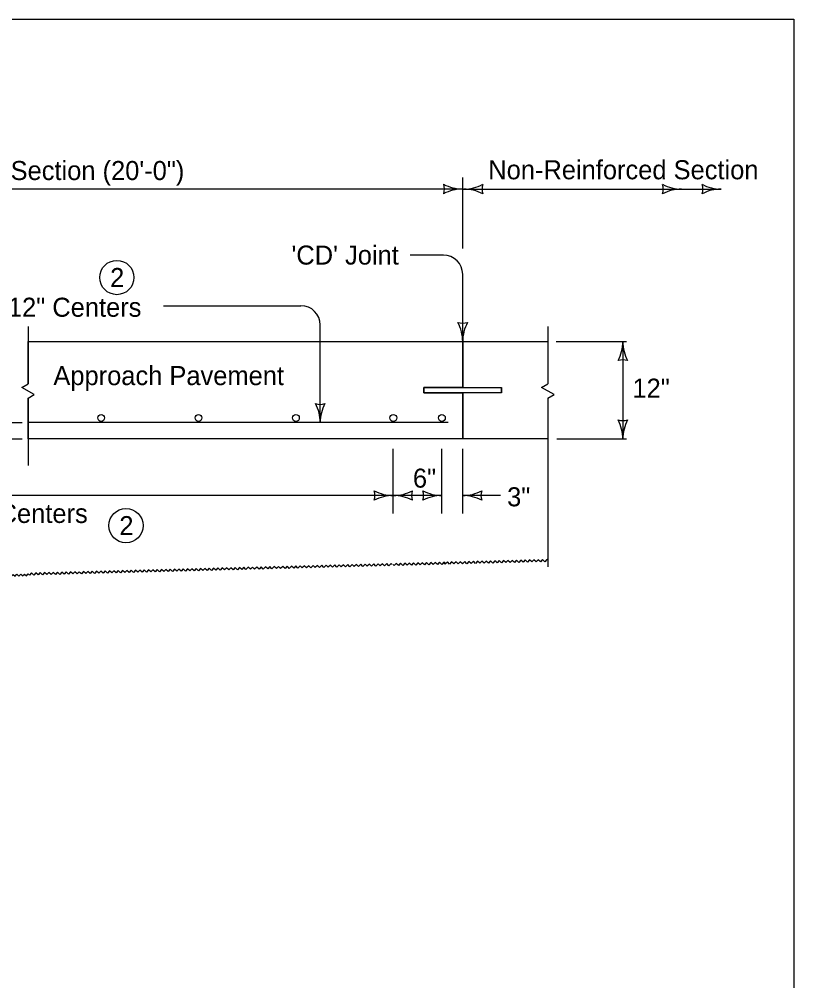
# Model space of a CAD drawing. Extents: x 10130 to 81668, y 5440 to 21644.
# Drawn here: x 12454 to 13268, y 8934 to 9944 of the extents above; entities that cross this region are included whole.
import ezdxf

# ---------------------------------------------------------------- set-up
doc = ezdxf.new("R2010")
doc.units = 0
for name, color, linetype in [('dsnStdBlockModified', 7, 'Continuous'), ('dsnStdBlockNotModified', 7, 'Continuous'), ('dsnStdBorder', 7, 'Continuous'), ('Level 3', 7, 'Continuous'), ('SheetBorder', 7, 'Continuous')]:
    doc.layers.add(name, color=color, linetype=linetype)

msp = doc.modelspace()

# ---------------------------------------------------------------- linework, layer by layer
at = {"layer": 'dsnStdBlockModified'}
for p, q in [((12919.6, 9703.1), (12919.6, 9777.8)), ((11951, 9765.7), (12919.6, 9765.7)), ((12919.6, 9765.6), (13191.2, 9765.6)), ((12899.4, 9696.3), (12864.5, 9696.3)), ((12919.6, 9605.5), (12919.6, 9676.1)), ((12605.1, 9643.1), (12749.7, 9643.1)), ((12769.9, 9520.3), (12769.9, 9622.9)), ((12462.9, 9561.1), (12462.9, 9605.5)), ((12462.9, 9605.5), (12919.6, 9605.5)), ((12462.9, 9605.5), (12919.6, 9605.5)), ((12919.6, 9605.5), (12919.6, 9557.2)), ((12919.6, 9605.5), (13009.1, 9605.5)), ((13017.9, 9605.4), (13091.7, 9605.4)), ((13087.9, 9605.4), (13087.9, 9503.1)), ((12462.9, 9561.1), (12462.9, 9561.1)), ((12919.6, 9557.2), (12878.7, 9557.2)), ((12878.7, 9557.2), (12878.7, 9551.5)), ((12878.7, 9557.2), (12878.7, 9551.5)), ((12960.5, 9551.5), (12960.5, 9557.2)), ((12462.9, 9503.2), (12462.9, 9545.9)), ((12878.7, 9551.5), (12919.6, 9551.5)), ((12919.6, 9551.5), (12919.6, 9503.2)), ((12433.7, 9520.3), (12456.6, 9520.3)), ((12433.7, 9503.2), (12456.6, 9503.2)), ((12919.6, 9503.2), (12462.9, 9503.2)), ((12919.6, 9503.2), (12462.9, 9503.2)), ((13009.1, 9503.2), (12919.6, 9503.2)), ((13018.4, 9503.1), (13091.7, 9503.1)), ((12846.7, 9424.7), (12846.7, 9492.7)), ((12897.8, 9424.7), (12897.8, 9492.7)), ((12919.6, 9424.7), (12919.6, 9492.7)), ((12846.7, 9443.7), (12023.9, 9443.7)), ((12897.8, 9443.7), (12846.7, 9443.7)), ((12886.4, 9443.7), (12846.7, 9443.7)), ((12959.4, 9443.7), (12919.6, 9443.7))]:
    msp.add_line(p, q, dxfattribs=at)
for points in [[(12462.9, 9545.9), (12469.4, 9549.7), (12456.3, 9557.3), (12462.9, 9561.1)], [(12901.1, 9372.6), (12899.9, 9373.7), (12897.7, 9371.4), (12895.3, 9373.6), (12893.1, 9371.3), (12890.8, 9373.5), (12888.6, 9371.2), (12886.2, 9373.4), (12884, 9371), (12881.7, 9373.3), (12879.5, 9370.9), (12877.1, 9373.1), (12874.9, 9370.8), (12872.6, 9373), (12870.4, 9370.7), (12868, 9372.9), (12865.8, 9370.6), (12863.5, 9372.8), (12861.3, 9370.5), (12858.9, 9372.7), (12856.7, 9370.3), (12854.4, 9372.5), (12852.2, 9370.2), (12849.8, 9372.4), (12847.6, 9370.1), (12846.4, 9371.2)], [(12954.7, 9374), (12953.5, 9375.2), (12951.3, 9372.8), (12949, 9375), (12946.8, 9372.7), (12944.4, 9374.9), (12942.2, 9372.6), (12939.9, 9374.8), (12937.7, 9372.5), (12935.3, 9374.7), (12933.1, 9372.4), (12930.8, 9374.6), (12928.6, 9372.2), (12926.2, 9374.4), (12924, 9372.1), (12921.7, 9374.3), (12919.5, 9372), (12917.1, 9374.2), (12914.9, 9371.9), (12912.6, 9374.1), (12910.4, 9371.8), (12908, 9374), (12905.8, 9371.6), (12903.5, 9373.9), (12901.3, 9371.5), (12900.1, 9372.6)], [(13009.3, 9375.5), (13008.1, 9376.6), (13005.9, 9374.2), (13003.6, 9376.5), (13001.4, 9374.1), (12999, 9376.3), (12996.8, 9374), (12994.5, 9376.2), (12992.3, 9373.9), (12989.9, 9376.1), (12987.7, 9373.8), (12985.4, 9376), (12983.2, 9373.7), (12980.8, 9375.9), (12978.6, 9373.5), (12976.3, 9375.8), (12974.1, 9373.4), (12971.7, 9375.6), (12969.5, 9373.3), (12967.2, 9375.5), (12965, 9373.2), (12962.6, 9375.4), (12960.4, 9373.1), (12958.1, 9375.3), (12955.9, 9372.9), (12954.7, 9374)], [(12517.8, 9362.6), (12516.7, 9363.7), (12514.5, 9361.4), (12512.1, 9363.6), (12509.9, 9361.3), (12507.6, 9363.5), (12505.4, 9361.2), (12503, 9363.4), (12500.8, 9361.1), (12498.5, 9363.3), (12496.3, 9360.9), (12493.9, 9363.2), (12491.7, 9360.8), (12489.4, 9363), (12487.2, 9360.7), (12484.8, 9362.9), (12482.6, 9360.6), (12480.3, 9362.8), (12478.1, 9360.5), (12475.7, 9362.7), (12473.5, 9360.3), (12471.2, 9362.6), (12469, 9360.2), (12466.6, 9362.4), (12464.4, 9360.1), (12463.2, 9361.2)], [(12572.4, 9364.1), (12571.3, 9365.2), (12569.1, 9362.8), (12566.7, 9365.1), (12564.5, 9362.7), (12562.2, 9364.9), (12560, 9362.6), (12557.6, 9364.8), (12555.4, 9362.5), (12553.1, 9364.7), (12550.9, 9362.4), (12548.5, 9364.6), (12546.3, 9362.2), (12544, 9364.5), (12541.8, 9362.1), (12539.4, 9364.3), (12537.2, 9362), (12534.9, 9364.2), (12532.7, 9361.9), (12530.3, 9364.1), (12528.1, 9361.8), (12525.8, 9364), (12523.6, 9361.7), (12521.2, 9363.9), (12519, 9361.5), (12517.8, 9362.6)], [(12627.1, 9365.5), (12625.9, 9366.6), (12623.7, 9364.3), (12621.3, 9366.5), (12619.1, 9364.2), (12616.8, 9366.4), (12614.6, 9364), (12612.2, 9366.2), (12610, 9363.9), (12607.7, 9366.1), (12605.5, 9363.8), (12603.1, 9366), (12600.9, 9363.7), (12598.6, 9365.9), (12596.4, 9363.6), (12594, 9365.8), (12591.8, 9363.4), (12589.5, 9365.6), (12587.3, 9363.3), (12584.9, 9365.5), (12582.7, 9363.2), (12580.4, 9365.4), (12578.2, 9363.1), (12575.8, 9365.3), (12573.6, 9363), (12572.4, 9364.1)], [(12681.7, 9366.9), (12680.5, 9368), (12678.3, 9365.7), (12675.9, 9367.9), (12673.7, 9365.6), (12671.4, 9367.8), (12669.2, 9365.5), (12666.8, 9367.7), (12664.6, 9365.3), (12662.3, 9367.6), (12660.1, 9365.2), (12657.7, 9367.4), (12655.5, 9365.1), (12653.2, 9367.3), (12651, 9365), (12648.6, 9367.2), (12646.4, 9364.9), (12644.1, 9367.1), (12641.9, 9364.7), (12639.5, 9367), (12637.3, 9364.6), (12635, 9366.8), (12632.8, 9364.5), (12630.4, 9366.7), (12628.2, 9364.4), (12627.1, 9365.5)], [(12736.3, 9368.3), (12735.1, 9369.5), (12732.9, 9367.1), (12730.6, 9369.3), (12728.3, 9367), (12726, 9369.2), (12723.8, 9366.9), (12721.5, 9369.1), (12719.2, 9366.8), (12716.9, 9369), (12714.7, 9366.6), (12712.4, 9368.9), (12710.1, 9366.5), (12707.8, 9368.7), (12705.6, 9366.4), (12703.3, 9368.6), (12701, 9366.3), (12698.7, 9368.5), (12696.5, 9366.2), (12694.2, 9368.4), (12691.9, 9366.1), (12689.6, 9368.3), (12687.4, 9365.9), (12685, 9368.1), (12682.8, 9365.8), (12681.7, 9366.9)], [(12790.9, 9369.8), (12789.7, 9370.9), (12787.5, 9368.6), (12785.2, 9370.8), (12782.9, 9368.4), (12780.6, 9370.6), (12778.4, 9368.3), (12776.1, 9370.5), (12773.8, 9368.2), (12771.5, 9370.4), (12769.3, 9368.1), (12767, 9370.3), (12764.7, 9368), (12762.4, 9370.2), (12760.2, 9367.8), (12757.9, 9370), (12755.6, 9367.7), (12753.3, 9369.9), (12751.1, 9367.6), (12748.8, 9369.8), (12746.5, 9367.5), (12744.2, 9369.7), (12742, 9367.4), (12739.7, 9369.6), (12737.4, 9367.2), (12736.3, 9368.3)], [(12845.5, 9371.2), (12844.3, 9372.3), (12842.1, 9370), (12839.8, 9372.2), (12837.5, 9369.9), (12835.2, 9372.1), (12833, 9369.7), (12830.7, 9371.9), (12828.5, 9369.6), (12826.1, 9371.8), (12823.9, 9369.5), (12821.6, 9371.7), (12819.4, 9369.4), (12817, 9371.6), (12814.8, 9369.3), (12812.5, 9371.5), (12810.2, 9369.1), (12807.9, 9371.4), (12805.7, 9369), (12803.4, 9371.2), (12801.1, 9368.9), (12798.8, 9371.1), (12796.6, 9368.8), (12794.3, 9371), (12792, 9368.7), (12790.9, 9369.8)], [(12426.5, 9359.4), (12427.4, 9360.4), (12429.4, 9358.4), (12431.4, 9360.5), (12433.4, 9358.5), (12435.3, 9360.6), (12437.4, 9358.6), (12439.3, 9360.7), (12441.3, 9358.7), (12443.3, 9360.8), (12445.3, 9358.8), (12447.2, 9360.9), (12449.3, 9359), (12451.2, 9361), (12453.2, 9359.1), (12455.2, 9361.1), (12457.2, 9359.2), (12459.1, 9361.2), (12461.2, 9359.3), (12463.1, 9361.3), (12464.1, 9360.3)]]:
    msp.add_lwpolyline(points, dxfattribs=at)
for centre, radius, start, end in [((12884, 9765.7), 16.4, 342.2666, 17.7333), ((12919.6, 9808.2), 42.5, 241.9275, 270), ((12920.7, 9808.1), 42.5, 270, 298.0725), ((12956.4, 9765.6), 16.4, 162.2666, 197.7334), ((13114, 9765.6), 16.4, 342.2666, 17.7333), ((13149.6, 9808.1), 42.5, 241.9275, 270), ((13155.6, 9765.6), 16.4, 342.2666, 17.7333), ((13191.2, 9808.1), 42.5, 241.9275, 270), ((12919.6, 9723.2), 42.5, 90, 118.0725), ((12920.7, 9723.1), 42.5, 61.9275, 90), ((13149.6, 9723.1), 42.5, 90, 118.0725), ((13191.2, 9723.1), 42.5, 90, 118.0725), ((12899.4, 9676.1), 20.2, 0, 90), ((12749.7, 9622.9), 20.2, 0, 90), ((12919.6, 9641.2), 16.4, 252.2666, 287.7333), ((12877.1, 9605.5), 42.5, 360, 28.0725), ((12962.1, 9605.5), 42.5, 151.9275, 180), ((13045.4, 9605.4), 42.5, 331.9275, 360), ((13130.4, 9605.4), 42.5, 180, 208.0725), ((13087.9, 9569.8), 16.4, 72.2666, 107.7334), ((12769.9, 9555.9), 16.4, 252.2666, 287.7333), ((12727.4, 9520.3), 42.5, 360, 28.0725), ((12812.4, 9520.3), 42.5, 151.9275, 180), ((13087.9, 9538.8), 16.4, 252.2666, 287.7333), ((13045.4, 9503.1), 42.5, 360, 28.0725), ((13130.4, 9503.1), 42.5, 151.9275, 180), ((12811, 9443.7), 16.4, 342.2666, 17.7333), ((12846.7, 9486.2), 42.5, 241.9275, 270), ((12846.7, 9401.2), 42.5, 90, 118.0725), ((12846.7, 9486.2), 42.5, 270, 298.0725), ((12846.7, 9401.2), 42.5, 61.9275, 90), ((12882.3, 9443.7), 16.4, 162.2666, 197.7334), ((12862.2, 9443.7), 16.4, 342.2666, 17.7333), ((12897.8, 9486.2), 42.5, 241.9275, 270), ((12897.8, 9401.2), 42.5, 90, 118.0725), ((12919.6, 9486.2), 42.5, 270, 298.0725), ((12919.6, 9401.2), 42.5, 61.9275, 90), ((12955.2, 9443.7), 16.4, 162.2666, 197.7334)]:
    msp.add_arc(centre, radius, start, end, dxfattribs=at)
at = {"layer": 'dsnStdBlockNotModified'}
for centre, radius, start, end in [((12846.7, 9486.2), 42.5, 270, 298.0725), ((12846.7, 9401.2), 42.5, 61.9275, 90), ((12882.3, 9443.7), 16.4, 162.2666, 197.7334), ((12862.2, 9443.7), 16.4, 342.2666, 17.7333), ((12897.8, 9486.2), 42.5, 241.9275, 270), ((12897.8, 9401.2), 42.5, 90, 118.0725)]:
    msp.add_arc(centre, radius, start, end, dxfattribs=at)
at = {"layer": 'dsnStdBorder'}
for p, q in [((12462.9, 9621.2), (12462.9, 9561.1)), ((13009.1, 9621.2), (13009.1, 9561.1)), ((12919.6, 9557.2), (12919.6, 9605.5)), ((12878.7, 9551.5), (12878.7, 9557.2)), ((12878.7, 9557.2), (12960.5, 9557.2)), ((12960.5, 9557.2), (12960.5, 9551.5)), ((12462.9, 9545.9), (12462.9, 9475.2)), ((12960.5, 9551.5), (12878.7, 9551.5)), ((12919.6, 9503.2), (12919.6, 9551.5)), ((13009.1, 9545.9), (13009.1, 9368.7)), ((12904.5, 9520.3), (12462.9, 9520.3))]:
    msp.add_line(p, q, dxfattribs=at)
for points in [[(12462.9, 9545.9), (12469.4, 9549.7), (12456.3, 9557.3), (12462.9, 9561.1)], [(13009.1, 9545.9), (13015.7, 9549.7), (13002.6, 9557.3), (13009.1, 9561.1)]]:
    msp.add_lwpolyline(points, dxfattribs=at)
for centre in [(12556.2, 9672.7), (12565.8, 9412.1)]:
    msp.add_circle(centre, 18, dxfattribs=at)
for centre, radius, start, end in [((13045.4, 9605.4), 42.5, 331.9275, 360), ((13130.4, 9605.4), 42.5, 180, 208.0725), ((13087.9, 9569.8), 16.4, 72.2666, 107.7334)]:
    msp.add_arc(centre, radius, start, end, dxfattribs=at)
at = {"layer": 'Level 3'}
for centre in [(12539.7, 9525.2), (12642, 9525.2), (12744.4, 9525.2), (12846.7, 9525.2), (12897.8, 9525.2)]:
    msp.add_circle(centre, 3.55, dxfattribs=at)
at = {"layer": 'SheetBorder'}
msp.add_lwpolyline([(10132.5, 9944), (13267.5, 9944), (13267.5, 7924), (10132.5, 7924)], close=True, dxfattribs=at)

# ---------------------------------------------------------------- texts
at = {"layer": 'dsnStdBlockModified'}
for s, p in [('Single Reinforced Section (20\'-0")', (12226, 9775.1)), ('Non-Reinforced Section', (12946.5, 9775.9)), ("'CD' Joint", (12739.7, 9686.3)), ('2', (12549.1, 9662.7)), ('#5 Bars At 12" Centers', (12309.4, 9631.5)), ('Approach Pavement', (12489.5, 9559.7)), ('12"', (13098, 9546.5)), ('6"', (12867.3, 9452)), ('3"', (12966.3, 9432.4)), ('#5 Bars At 12" max. Centers', (12187.6, 9414.9)), ('2', (12558.8, 9402.1))]:
    msp.add_text(s, height=20, dxfattribs=at).set_placement(p)

doc.saveas('drawing.dxf')
